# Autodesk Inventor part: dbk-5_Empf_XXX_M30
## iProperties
Shininess: 20.0
Length Units: 11269
Angle Units: 11279
Time Units: 11290
Mass Units: 11283
Length Display Precision: 2
Angle Display Precision: 2
Company: Microsonic
Part Number: dbk-5_Empf_XXX_M30
Material: Nichtrostender Stahl - 440C
Document SubType Name: Modellieren
Description: dbk-5/Empf/XXX/M30
Checked By: Alves
Created: 2005-08
Designer: Ohle
Manufacturer: Standard
Standards Organization: Custom
Density: 0.0
Volumn: 0.0
Area: 0.0
PropertySet Name: Model Information
Control State: 0
Master: False
Checked Out: False
Last Check In By: Kramp
Last Check In Date: 2005-08-10
BESTELLNUMMER: dbk-5/Empf/XXX/M30
ME: ST
Title: wms Sensoren
Author: Ohle
Comments: keine Bemerkung
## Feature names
1. dbk-5 Empfänger [Revolution]
2. Pole [Extrusion]
3. Rundung Pole [Fillet]
4. Verdrehsicherung [Extrusion]
5. LED [Revolution]
6. Kabel Empfänger [Extrusion]
7. Litzen Empfänger [Extrusion]
